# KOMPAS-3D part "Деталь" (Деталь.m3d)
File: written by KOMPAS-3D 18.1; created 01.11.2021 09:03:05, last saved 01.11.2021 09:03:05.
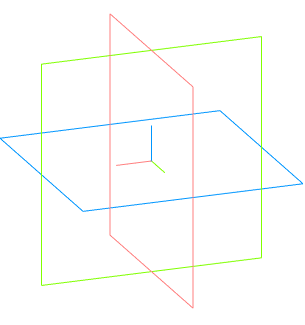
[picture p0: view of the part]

Document properties: Автор: 111; Полное имя файла: C:\Users\admin\Desktop\ffb\Деталь.m3d

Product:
- Part/product: Деталь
